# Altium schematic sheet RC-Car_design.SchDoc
size A
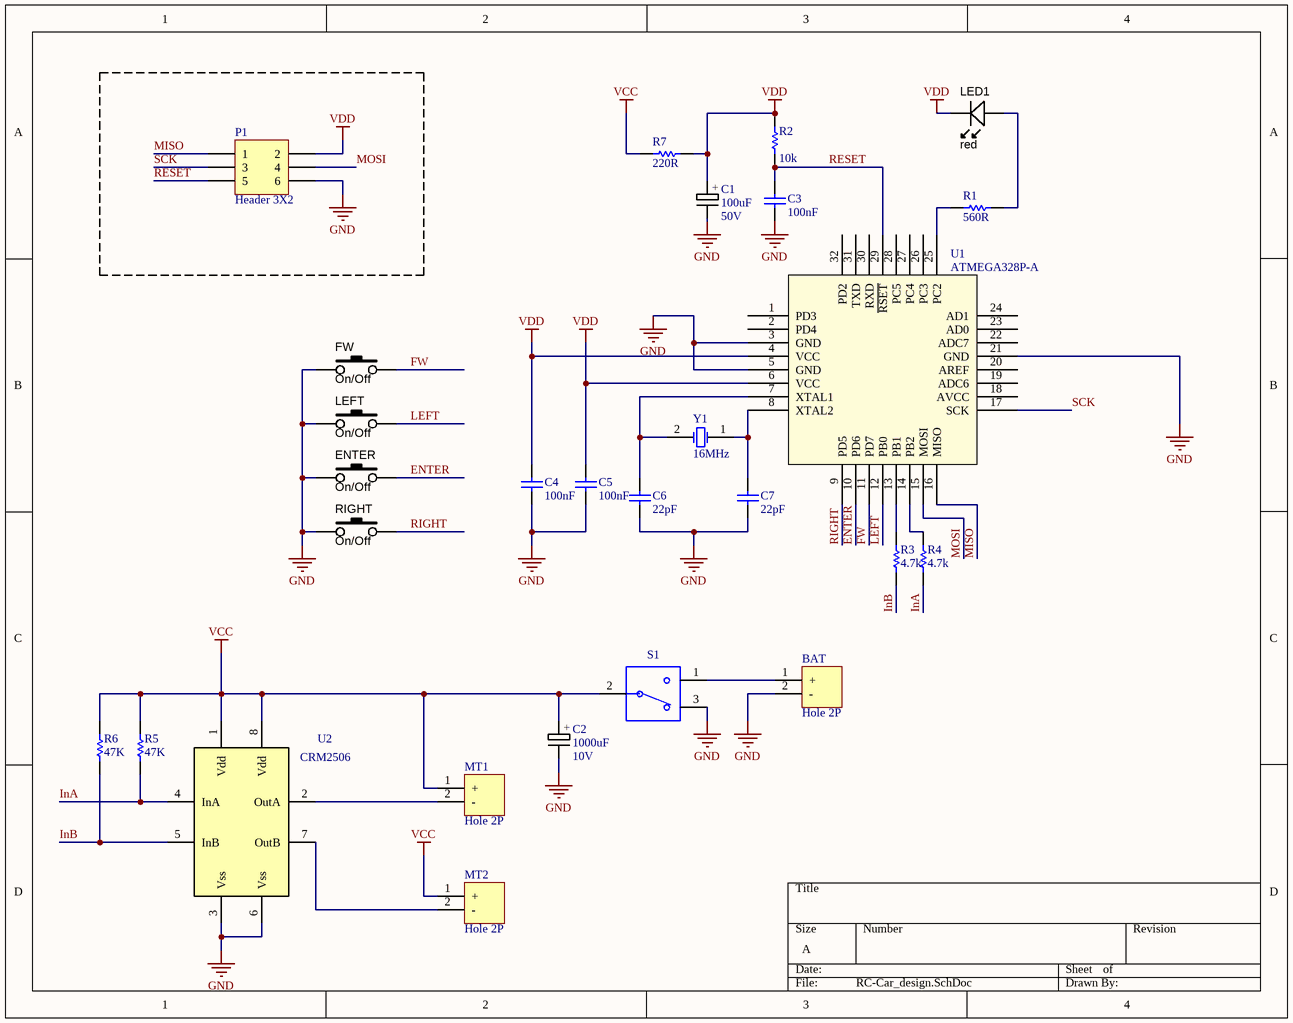
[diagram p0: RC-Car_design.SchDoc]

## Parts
BAT  Hole 2P  [Header_pitch7mm_hole1.2mm]
C1  value 100uF  voltage: 50V  [Picth3.5_D8_H12_Al_condensor]
C2  value 1000uF  voltage: 10V  [Picth3.5_D8_H12_Al_condensor]
C3  value 100nF  [C0402]  (hidden comment: Cap Semi)
C4  value 100nF  [R0402]  (hidden comment: Cap Semi)
C5  value 100nF  [R0402]  (hidden comment: Cap Semi)
C6  value 22pF  [C0402]  (hidden comment: Cap Semi)
C7  value 22pF  [C0402]  (hidden comment: Cap Semi)
ENTER  Function: On/Off  [TACT_SWITCH_TL-1105-C]  (hidden comment: EVQ-PQHB55)
FW  Function: On/Off  [TACT_SWITCH_TL-1105-C]  (hidden comment: EVQ-PQHB55)
LED1  red  [HDR_1x2_LED]
LEFT  Function: On/Off  [TACT_SWITCH_TL-1105-C]  (hidden comment: EVQ-PQHB55)
MT1  Hole 2P  [Header_pitch12mm_hole1.2mm]
MT2  Hole 2P  [Header_pitch12mm_hole1.2mm]
P1  Header 3X2  [HDR2X3]
R1  value 560R  [Metal Film Resistor_2X12mm]  (hidden comment: Res Semi)
R2  value 10k  [R0402]  (hidden comment: Res0402)
R3  value 4.7k  [Metal Film Resistor_2X12mm]  (hidden comment: Res Semi)
R4  value 4.7k  [Metal Film Resistor_2X12mm]  (hidden comment: Res Semi)
R5  value 47K  [Metal Film Resistor_2X12mm]  (hidden comment: Res Semi)
R6  value 47K  [Metal Film Resistor_2X12mm]  (hidden comment: Res Semi)
R7  value 220R  [Metal Film Resistor_2X12mm]  (hidden comment: Res Semi)
RIGHT  Function: On/Off  [TACT_SWITCH_TL-1105-C]  (hidden comment: EVQ-PQHB55)
S1  1825116-1  [SS-12D1505-G 2]  (value not drawn)
U1  ATMEGA328P-A  [ATMEGA328P]
U2  CRM2506  [SOIC127P600X175-8AN]
Y1  16MHz  [XTAL16]

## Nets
GND: BAT.2(-) C1.2 C2.2 C3.2 C4.1 C5.1 C6.2 C7.2 ENTER.1 FW.1 LEFT.1 P1.6 RIGHT.1 S1.3 U1.3(GND) U1.5(GND) U1.21(GND) U2.3(Vss) U2.6(Vss)
VCC: C2.1 MT1.1(+) MT2.1(+) R5.1 R6.1 R7.2 S1.2 U2.1(Vdd) U2.8(Vdd)
VDD: C1.1 C4.2 C5.2 LED1.K P1.2 R2.2 R7.1 U1.4(VCC) U1.6(VCC)
ENTER: ENTER.2 U1.10(PD6)
FW: FW.2 U1.11(PD7)
InA: R4.1 R5.2 U2.4(InA)
InB: R3.1 R6.2 U2.5(InB)
LEFT: LEFT.2 U1.12(PB0)
MISO: P1.1 U1.16(MISO)
MOSI: P1.4 U1.15(MOSI)
RESET: C3.1 P1.5 R2.1 U1.29(~{RSET})
RIGHT: RIGHT.2 U1.9(PD5)
SCK: P1.3 U1.17(SCK)
NetBAT_1: BAT.1(+) S1.1
NetC6_1: C6.1 U1.7(XTAL1) Y1.2(OSC2)
NetC7_1: C7.1 U1.8(XTAL2) Y1.1(OSC1)
NetLED1_A: LED1.A R1.1
NetMT1_2: MT1.2(-) U2.2(OutA)
NetMT2_2: MT2.2(-) U2.7(OutB)
NetR1_2: R1.2 U1.25(PC2)
NetR3_2: R3.2 U1.13(PB1)
NetR4_2: R4.2 U1.14(PB2)

Not connected (* = marked no-connect by the designer): U1 1(PD3) 2(PD4) 18(AVCC) 19(ADC6) 20(AREF) 22(ADC7) 23(AD0) 24(AD1) 26(PC3) 27(PC4) 28(PC5) 30(RXD) 31(TXD) 32(PD2)

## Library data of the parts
BAT MT1 MT2 = Hole 2P: Header, 2-Pin
C1 C2 = CAP ELEC6.3*4.2
C3-C7 = Cap Semi: Capacitor (Semiconductor SIM Model)
ENTER FW LEFT RIGHT = SMD4*4*1.5 4p: Low-profile captive tact switch; Manufacturer 1: Panasonic - ECG; Ratings: 1.6 Newton; Switch Function: Off-Mom; Contact Rating @ Voltage: 0.02A @ 15VDC; Outline: 4.50mm x 4.50mm; Operating Force: 160gf; SCDType: spec
LED1 = LED_SMD_Yellow_0603_150mcd: LED 0603 SMD Yellow 590nm 150mcd 20mA
P1 = Header 3X2: Header, 3-Pin, Dual row
R1 R3-R7 = Res Semi: Semiconductor Resistor
R2 = Res0402: Semiconductor Resistor
S1 = 1825116-1: Slide Switch SPDT Through Hole, Right Angle; Manufacturer: ITT C&K; Manufacturer Part Number: SS12D1505G2; Actuator Material: Nylon,Polyamide; Current Rating: 300mA; Voltage Rating (DC): 6V; Operating Force: 200gf; Contact Style: Non-Shorting; Electrical Life: 10000Cycles; Illumination Type: Non-Illuminated; Switch Travel: 2mm; Switch Function: On-On; Actuator Type: Standard
U1 = ATMEGA328P-A: IC, SWITCH, SPDT ANA, SMD; Manufacturer: Microchip / Atmel; Manufacturer Part Number: ATMEGA328PB-AUR; Frequency: 20MHz; Interface: I2C,SPI,UART,USART; Number of I/Os: 27; Oscillator Type: Internal; RAM Size: 2KB; Number of Timers/Counters: 5; Watchdog Timer: Yes; Memory Type: FLASH; Memory Size: 32KB; Peripherals: Brown-out Detect/Reset,POR,PWM,WDT; Min Supply Voltage: 1.8V; Max Supply Voltage: 5.5V; Core Architecture: AVR; Operating Supply Voltage: 5V
Y1 = XTAL: Crystal Oscillator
